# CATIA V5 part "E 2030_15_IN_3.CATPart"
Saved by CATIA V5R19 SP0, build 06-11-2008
Material "Plastic": density 1200 kg/m3, Young's modulus 2.2e+09 Pa, Poisson ratio 0.38, thermal expansion 6.84e-05 1/K
Bounding box of the stored display mesh (mm): x 37.75 to 52.85, y -7.54 to 7.54, z -2 to 0
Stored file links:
  G:\UTB\Kombinované\Bakalářská práce\Catia\FORMA\E 2030_15_IN_3.CATPart
  D:\Aplikace\CATIA\Nová složka\win_b64\startup\materials\Catalog.CATMaterial
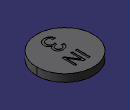
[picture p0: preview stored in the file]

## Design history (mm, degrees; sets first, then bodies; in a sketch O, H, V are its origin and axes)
Body1 "E 2030_15_IN_1-8" (main body)
  Solid1: solid without history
